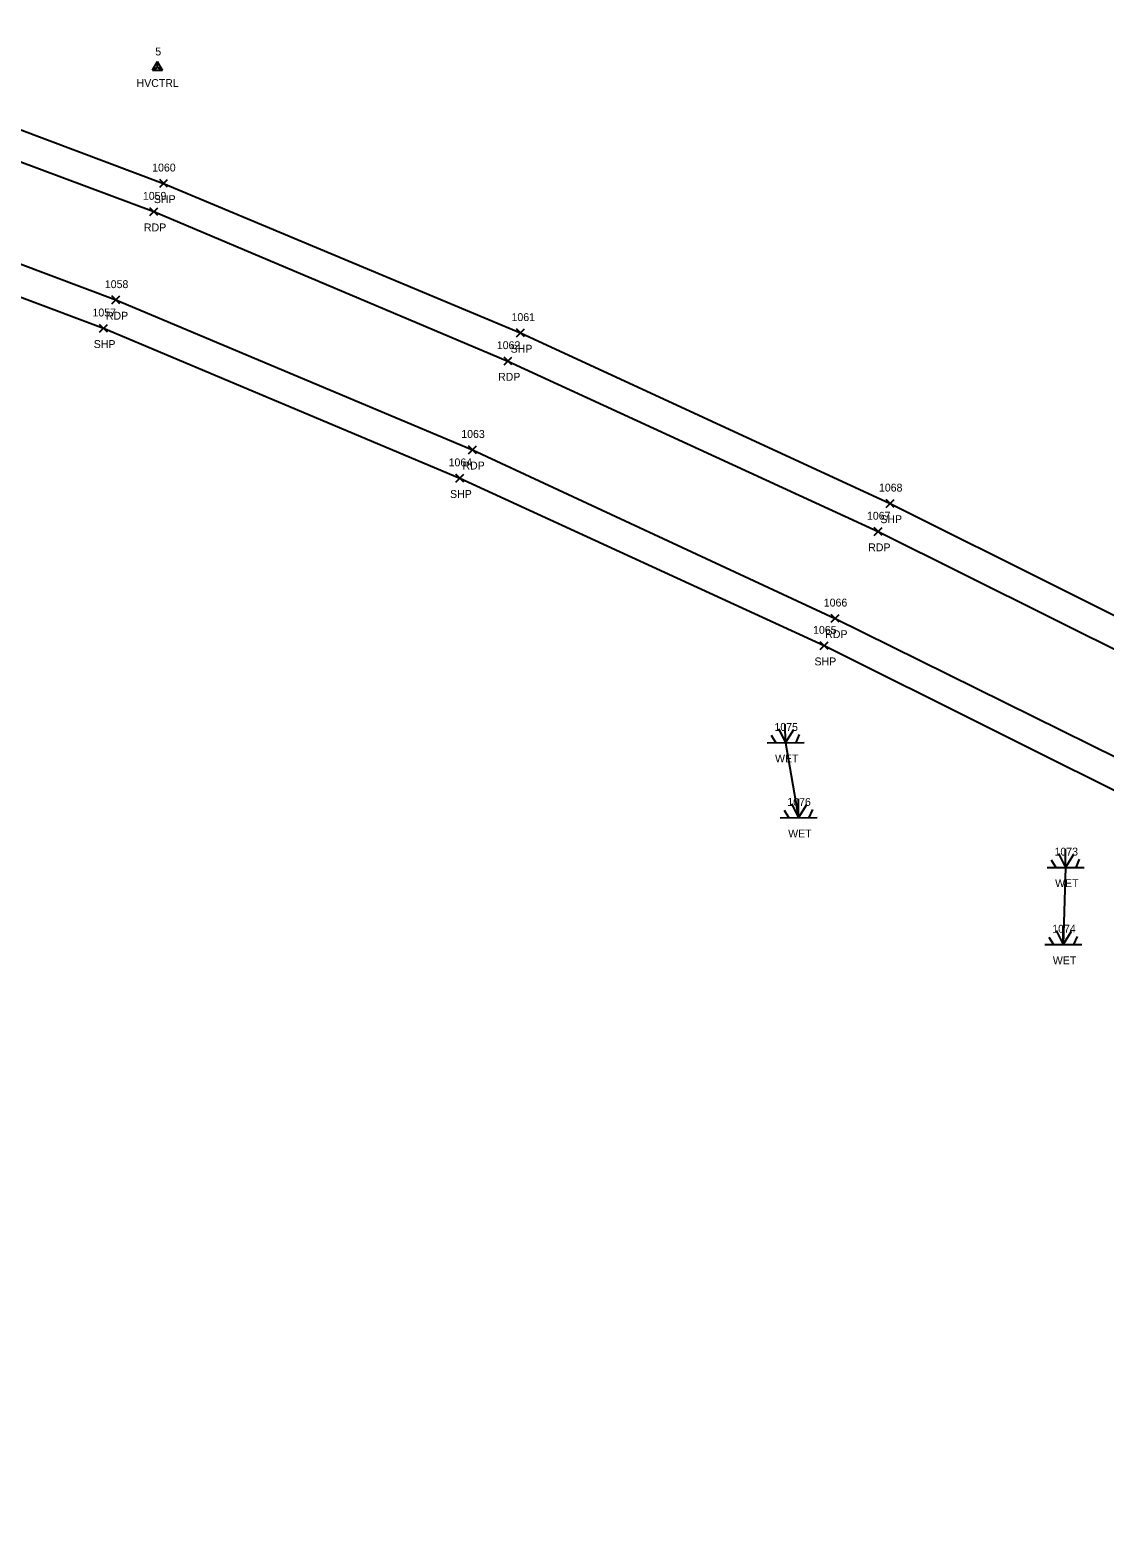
# Model space of a CAD drawing. Extents: x 1519347 to 1522636, y 378779 to 379832.
# Drawn here: x 1521601.3 to 1521873.5, y 379160.8 to 379542.8 of the extents above; entities that cross this region are included whole.
import ezdxf

# ---------------------------------------------------------------- set-up
doc = ezdxf.new("R2010")
doc.units = 0
for name, color, linetype in [('C_A', 7, 'Continuous'), ('C_I', 7, 'Continuous'), ('CPSM', 7, 'Continuous'), ('L_A', 7, 'Continuous'), ('L_I', 7, 'Continuous'), ('LWET', 7, 'Continuous'), ('P_A', 7, 'Continuous'), ('P_I', 7, 'Continuous'), ('P_TIC', 7, 'Continuous'), ('PE', 7, 'Continuous'), ('PSP', 7, 'Continuous')]:
    doc.layers.add(name, color=color, linetype=linetype)

msp = doc.modelspace()

# ---------------------------------------------------------------- linework, layer by layer
at = {"layer": 'CPSM'}
for p, q in [((1521632.29, 379532.65), (1521633.54, 379534.82)), ((1521632.29, 379532.65), (1521633.54, 379533.38)), ((1521632.29, 379532.65), (1521634.79, 379532.65)), ((1521634.79, 379532.65), (1521633.54, 379534.82)), ((1521633.54, 379533.38), (1521633.54, 379534.82)), ((1521633.54, 379533.38), (1521633.54, 379533.38)), ((1521633.54, 379533.38), (1521634.79, 379532.65))]:
    msp.add_line(p, q, dxfattribs=at)
at = {"layer": 'LWET'}
for p, q in [((1521788.97, 379364.14), (1521790.13, 379362.21)), ((1521790.79, 379365.8), (1521792.61, 379362.27)), ((1521792.58, 379362.24), (1521792.55, 379366.98)), ((1521794.59, 379365.52), (1521792.61, 379362.27)), ((1521796.08, 379364.31), (1521795.2, 379362.27)), ((1521787.92, 379362.21), (1521797.3, 379362.27)), ((1521792.73, 379362.42), (1521792.61, 379362.42)), ((1521792.29, 379345.15), (1521793.45, 379343.22)), ((1521794.11, 379346.8), (1521795.93, 379343.28)), ((1521795.9, 379343.25), (1521795.87, 379347.99)), ((1521797.91, 379346.53), (1521795.93, 379343.28)), ((1521799.4, 379345.32), (1521798.52, 379343.28)), ((1521791.24, 379343.22), (1521800.61, 379343.28)), ((1521796.05, 379343.43), (1521795.93, 379343.43)), ((1521861.72, 379334.2), (1521863.54, 379330.67)), ((1521863.51, 379330.65), (1521863.48, 379335.39)), ((1521865.52, 379333.93), (1521863.54, 379330.67)), ((1521858.85, 379330.62), (1521868.22, 379330.67)), ((1521859.9, 379332.55), (1521861.06, 379330.62)), ((1521863.66, 379330.83), (1521863.54, 379330.83)), ((1521867.01, 379332.71), (1521866.13, 379330.67)), ((1521861.14, 379314.67), (1521862.96, 379311.14)), ((1521862.93, 379311.11), (1521862.91, 379315.85)), ((1521864.95, 379314.39), (1521862.96, 379311.14)), ((1521858.28, 379311.09), (1521867.65, 379311.14)), ((1521859.33, 379313.01), (1521860.48, 379311.09)), ((1521863.09, 379311.3), (1521862.96, 379311.3)), ((1521866.44, 379313.18), (1521865.56, 379311.14))]:
    msp.add_line(p, q, dxfattribs=at)
for points in [[(1521792.58, 379362.24), (1521795.9, 379343.25)], [(1521863.51, 379330.65), (1521862.93, 379311.11)]]:
    msp.add_lwpolyline(points, dxfattribs=at)
at = {"layer": 'P_TIC'}
for points in [[(1521634.1, 379502.97), (1521636.1, 379504.97)], [(1521636.1, 379502.97), (1521634.1, 379504.97)], [(1521631.62, 379495.8), (1521633.62, 379497.8)], [(1521633.62, 379495.8), (1521631.62, 379497.8)], [(1521621.97, 379473.43), (1521623.97, 379475.43)], [(1521623.97, 379473.43), (1521621.97, 379475.43)], [(1521618.86, 379466.25), (1521620.86, 379468.25)], [(1521620.86, 379466.25), (1521618.86, 379468.25)], [(1521724.46, 379465.08), (1521726.46, 379467.08)], [(1521726.46, 379465.08), (1521724.46, 379467.08)], [(1521721.31, 379457.96), (1521723.31, 379459.96)], [(1521723.31, 379457.96), (1521721.31, 379459.96)], [(1521712.3, 379435.47), (1521714.3, 379437.47)], [(1521714.3, 379435.47), (1521712.3, 379437.47)], [(1521709.1, 379428.27), (1521711.1, 379430.27)], [(1521711.1, 379428.27), (1521709.1, 379430.27)], [(1521818.09, 379421.88), (1521820.09, 379423.88)], [(1521820.09, 379421.88), (1521818.09, 379423.88)], [(1521815.06, 379414.75), (1521817.06, 379416.75)], [(1521817.06, 379414.75), (1521815.06, 379416.75)], [(1521804.17, 379392.75), (1521806.17, 379394.75)], [(1521806.17, 379392.75), (1521804.17, 379394.75)], [(1521801.41, 379385.84), (1521803.41, 379387.84)], [(1521803.41, 379385.84), (1521801.41, 379387.84)]]:
    msp.add_lwpolyline(points, dxfattribs=at)
at = {"layer": 'PE'}
for points in [[(1521529.39, 379535.32), (1521632.62, 379496.8), (1521722.31, 379458.96), (1521816.06, 379415.75), (1521903.5, 379372.19), (1521985.15, 379327.91), (1522068.34, 379279.51), (1522152.8, 379226.58), (1522231.81, 379172.75), (1522311.43, 379114.1), (1522387.62, 379054.41), (1522460.96, 378992.6), (1522530.24, 378930.24), (1522627.42, 378835.6)], [(1521521.96, 379512.45), (1521622.97, 379474.43), (1521713.3, 379436.47), (1521805.17, 379393.75), (1521891.16, 379351.25), (1521973.22, 379306.84), (1522055.83, 379258.59), (1522137.28, 379207.8), (1522217.99, 379153.03), (1522296.46, 379094.97), (1522371.63, 379036.1), (1522445.19, 378974.11), (1522514.07, 378912.19), (1522609.78, 378819.15)]]:
    msp.add_lwpolyline(points, dxfattribs=at)
at = {"layer": 'PSP'}
for points in [[(1521531.82, 379542.79), (1521635.1, 379503.97), (1521725.46, 379466.08), (1521819.09, 379422.88), (1521907.05, 379378.96), (1521988.73, 379335.06), (1522072.92, 379286.87), (1522157.1, 379232.77), (1522235.26, 379178.41), (1522315.3, 379119.36), (1522391.65, 379059.53), (1522465.18, 378997.47), (1522534.68, 378934.98), (1522631.83, 378840.12)], [(1521519.02, 379505.15), (1521619.86, 379467.25), (1521710.1, 379429.27), (1521802.41, 379386.84), (1521887.29, 379344.47), (1521969.86, 379299.81), (1522051.39, 379251.77), (1522132.8, 379200.77), (1522213.2, 379146), (1522291.37, 379088.51), (1522366.45, 379029.85), (1522439.83, 378967.41), (1522509.25, 378905.3), (1522537.61, 378878.43), (1522603.87, 378813.19)]]:
    msp.add_lwpolyline(points, dxfattribs=at)

# ---------------------------------------------------------------- texts
at = {"layer": 'C_A'}
msp.add_text('HVCTRL', height=2, dxfattribs=at).set_placement((1521628.24, 379528.38))
at = {"layer": 'C_I'}
msp.add_text('5', height=2, dxfattribs=at).set_placement((1521632.98, 379536.38))
at = {"layer": 'L_A'}
for p in [(1521789.96, 379357.24), (1521793.28, 379338.25), (1521860.89, 379325.65), (1521860.31, 379306.11)]:
    msp.add_text('WET', height=2, dxfattribs=at).set_placement(p)
at = {"layer": 'L_I'}
for s, p in [('1075', (1521789.81, 379365.24)), ('1076', (1521793.07, 379346.25)), ('1073', (1521860.74, 379333.65)), ('1074', (1521860.16, 379314.11))]:
    msp.add_text(s, height=2, dxfattribs=at).set_placement(p)
at = {"layer": 'P_A'}
for s, p in [('SHP', (1521632.63, 379498.97)), ('RDP', (1521630.11, 379491.8)), ('RDP', (1521620.46, 379469.43)), ('SHP', (1521617.39, 379462.25)), ('SHP', (1521722.99, 379461.08)), ('RDP', (1521719.8, 379453.96)), ('RDP', (1521710.78, 379431.47)), ('SHP', (1521707.64, 379424.27)), ('SHP', (1521816.62, 379417.88)), ('RDP', (1521813.55, 379410.75)), ('RDP', (1521802.66, 379388.75)), ('SHP', (1521799.95, 379381.84))]:
    msp.add_text(s, height=2, dxfattribs=at).set_placement(p)
at = {"layer": 'P_I'}
for s, p in [('1060', (1521632.19, 379506.97)), ('1059', (1521629.84, 379499.8)), ('1058', (1521620.2, 379477.43)), ('1057', (1521617.08, 379470.25)), ('1061', (1521723.21, 379469.08)), ('1062', (1521719.49, 379461.96)), ('1063', (1521710.48, 379439.47)), ('1064', (1521707.28, 379432.27)), ('1068', (1521816.27, 379425.88)), ('1067', (1521813.24, 379418.75)), ('1066', (1521802.3, 379396.75)), ('1065', (1521799.59, 379389.84))]:
    msp.add_text(s, height=2, dxfattribs=at).set_placement(p)

doc.saveas('drawing.dxf')
